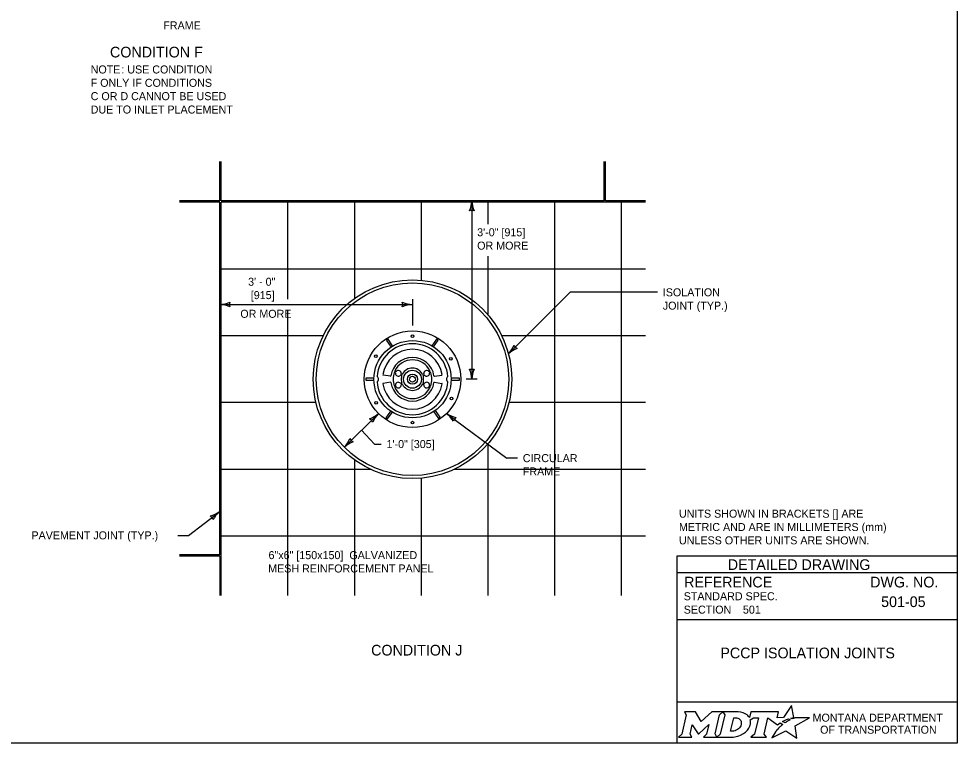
# Model space of a CAD drawing. Extents: x 49991.4 to 50021, y 49987.6 to 50011.4.
# Drawn here: x 50009.72 to 50016.75, y 49987.8 to 49993.22 of the extents above; entities that cross this region are included whole.
import ezdxf

# ---------------------------------------------------------------- set-up
doc = ezdxf.new("R2010")
doc.units = 0
for name, color, linetype in [('Default', 7, 'Continuous'), ('Level 1', 7, 'Continuous'), ('Level 15', 7, 'Continuous'), ('Level 2', 7, 'Continuous'), ('Level 3', 7, 'Continuous'), ('Level 4', 7, 'Continuous'), ('Level 5', 7, 'Continuous'), ('W35', 7, 'Continuous')]:
    doc.layers.add(name, color=color, linetype=linetype)

msp = doc.modelspace()

# ---------------------------------------------------------------- linework, layer by layer
at = {"layer": 'Default'}
for points in [[(50015.5126, 49987.9811), (50015.5023, 49987.9867), (50015.5139, 49987.9895), (50015.5255, 49987.9915), (50015.5081, 49988.0816), (50015.4486, 49987.9903), (50015.4013, 49987.9896), (50015.4116, 49988.0337), (50015.2024, 49988.0338), (50015.1923, 49987.9913), (50015.1865, 49987.9996)], [(50014.7056, 49988.0338), (50014.7197, 49988.0104), (50014.6862, 49987.8671), (50014.6605, 49987.8446), (50014.7621, 49987.8446), (50014.7486, 49987.8674), (50014.7648, 49987.9375), (50014.8085, 49987.8685), (50014.8138, 49987.8685), (50014.8889, 49987.938), (50014.8725, 49987.8669), (50014.8478, 49987.8449), (50014.9494, 49987.8449), (50014.9356, 49987.8682), (50014.9688, 49988.0106)], [(50014.9688, 49988.0106), (50014.9941, 49988.0338), (50014.9117, 49988.0338), (50014.8321, 49987.9608), (50014.7876, 49988.0335), (50014.7056, 49988.0338)], [(50015.1077, 49988.0338), (50014.9941, 49988.0338), (50015.0088, 49988.0109), (50014.9749, 49987.8671), (50014.9494, 49987.8449), (50015.06, 49987.8449)], [(50015.1317, 49987.9471), (50015.1305, 49987.939), (50015.1273, 49987.9297), (50015.1231, 49987.9215), (50015.1175, 49987.914), (50015.111, 49987.9071), (50015.1031, 49987.9008), (50015.0948, 49987.8961), (50015.0857, 49987.8922), (50015.0766, 49987.8899), (50015.0674, 49987.889), (50015.0515, 49987.889), (50015.0751, 49987.989), (50015.0911, 49987.989), (50015.0987, 49987.9884), (50015.1063, 49987.9865), (50015.1129, 49987.9835), (50015.119, 49987.9793), (50015.1238, 49987.9743), (50015.1275, 49987.9683), (50015.1302, 49987.9621), (50015.1318, 49987.9547), (50015.1318, 49987.9517), (50015.1317, 49987.9471)], [(50015.1991, 49987.9747), (50015.2237, 49987.9878), (50015.2606, 49987.9878), (50015.232, 49987.8673), (50015.2045, 49987.8446), (50015.3207, 49987.8446), (50015.3037, 49987.8675), (50015.3319, 49987.9877), (50015.4032, 49987.936), (50015.4243, 49987.9511), (50015.444, 49987.9402)], [(50015.3882, 49987.8843), (50015.3729, 49987.8599), (50015.3682, 49987.8524), (50015.3624, 49987.8438), (50015.3601, 49987.8395), (50015.4654, 49987.8926), (50015.5493, 49987.8375), (50015.5362, 49987.9302), (50015.6431, 49987.9886), (50015.5938, 49987.9894), (50015.5637, 49987.9898), (50015.5429, 49987.9901), (50015.5361, 49987.9886), (50015.5312, 49987.9874), (50015.5228, 49987.9851), (50015.5126, 49987.9811)], [(50015.4622, 49987.9535), (50015.4598, 49987.9518), (50015.4415, 49987.9614), (50015.4518, 49987.9671), (50015.4559, 49987.9693), (50015.4645, 49987.9733), (50015.4702, 49987.9759), (50015.4781, 49987.9789), (50015.4854, 49987.9816), (50015.4972, 49987.9742), (50015.4932, 49987.9721), (50015.4886, 49987.9696), (50015.4844, 49987.9674), (50015.4794, 49987.9645), (50015.4775, 49987.9634), (50015.4748, 49987.9618), (50015.4723, 49987.9604), (50015.47, 49987.9588), (50015.4674, 49987.957), (50015.4647, 49987.9552), (50015.4622, 49987.9535)], [(50015.1057, 49987.8522), (50015.1141, 49987.8548), (50015.1271, 49987.8602), (50015.1475, 49987.8712)], [(50015.4021, 49987.9004), (50015.4021, 49987.9004)]]:
    msp.add_lwpolyline(points, dxfattribs=at)
for centre, radius, start, end in [((50015.0868, 49987.9727), 0.1183, 300.91025, 339.13831), ((50015.1308, 49987.9554), 0.0709, 339.53292, 15.85821)]:
    msp.add_arc(centre, radius, start, end, dxfattribs=at)
for centre, major_axis, ratio, start_param, end_param in [((50015.1056, 49987.9864), (0.0834, -0.0037), 0.568097, 0.61298, 1.570796), ((50015.1612, 49987.9937), (0.0361, -0.0295), 0.469099, 1.225588, 1.570796), ((50015.4119, 49987.9106), (-0.0098, -0.0102), 0.016458, 3.141593, 6.279097), ((50015.4329, 49987.9305), (-0.0112, -0.0097), 0.021651, 3.157348, 6.283185), ((50015.0603, 49987.9932), (0, 0.1484), 0.987302, 3.139398, 3.456847), ((50015.3952, 49987.8923), (-0.00694, -0.00806), 0.008222, 0, 3.137361)]:
    msp.add_ellipse(centre, major_axis=major_axis, ratio=ratio, start_param=start_param, end_param=end_param, dxfattribs=at)
at = {"layer": 'Level 1'}
for p, q in [((50011.2232, 49991.862), (50011.2232, 49992.1547)), ((50011.2352, 49991.862), (50011.2352, 49992.1547)), ((50014.1032, 49991.862), (50014.1032, 49992.1547)), ((50014.1152, 49991.862), (50014.1152, 49992.1547)), ((50011.2232, 49991.862), (50010.9216, 49991.862)), ((50014.1032, 49991.862), (50011.2352, 49991.862)), ((50014.4142, 49991.862), (50014.1152, 49991.862)), ((50011.2232, 49991.85), (50010.9216, 49991.85)), ((50011.2232, 49989.8793), (50011.2232, 49991.85)), ((50014.4142, 49991.85), (50011.2352, 49991.85)), ((50011.2352, 49988.9044), (50011.2352, 49991.85)), ((50012.5032, 49990.548), (50012.4486, 49990.5557)), ((50012.5388, 49990.5737), (50012.5347, 49990.5754)), ((50012.5421, 49990.5816), (50012.538, 49990.5833)), ((50012.5865, 49990.5539), (50012.5813, 49990.5561)), ((50012.5898, 49990.5619), (50012.5846, 49990.564)), ((50012.746, 49990.5619), (50012.7512, 49990.564)), ((50012.7493, 49990.5539), (50012.7544, 49990.5561)), ((50012.7937, 49990.5816), (50012.7978, 49990.5833)), ((50012.797, 49990.5737), (50012.8011, 49990.5754)), ((50012.8325, 49990.548), (50012.8871, 49990.5557)), ((50012.5032, 49990.5017), (50012.4486, 49990.494)), ((50012.5388, 49990.476), (50012.5347, 49990.4743)), ((50012.5421, 49990.4681), (50012.538, 49990.4664)), ((50012.5865, 49990.4958), (50012.5813, 49990.4937)), ((50012.5898, 49990.4879), (50012.5846, 49990.4857)), ((50012.746, 49990.4879), (50012.7512, 49990.4857)), ((50012.7493, 49990.4958), (50012.7544, 49990.4937)), ((50012.7937, 49990.4681), (50012.7978, 49990.4664)), ((50012.797, 49990.476), (50012.8011, 49990.4743)), ((50012.8325, 49990.5017), (50012.8871, 49990.494)), ((50011.2232, 49989.209), (50011.2232, 49989.8793)), ((50011.2232, 49989.209), (50010.9216, 49989.209)), ((50011.2232, 49989.1997), (50010.9216, 49989.1997)), ((50011.2232, 49989.1997), (50011.2232, 49988.9044))]:
    msp.add_line(p, q, dxfattribs=at)
msp.add_lwpolyline([(49999.3835, 49998.9992), (50016.7501, 49998.9992), (50016.7501, 49987.7988), (49999.3835, 49987.7988)], close=True, dxfattribs=at)
for points in [[(50012.5195, 49990.7743), (50012.4847, 49990.824), (50012.4723, 49990.8153), (50012.5071, 49990.7657)], [(50012.5195, 49990.7743), (50012.4847, 49990.824), (50012.4723, 49990.8153), (50012.5071, 49990.7657)], [(50012.8258, 49990.7669), (50012.8606, 49990.8165), (50012.8482, 49990.8252), (50012.8134, 49990.7755)], [(50012.8258, 49990.7669), (50012.8606, 49990.8165), (50012.8482, 49990.8252), (50012.8134, 49990.7755)], [(50012.3791, 49990.5328), (50012.3185, 49990.5328), (50012.3185, 49990.5177), (50012.3791, 49990.5177)], [(50012.9596, 49990.5169), (50013.0202, 49990.5169), (50013.0202, 49990.532), (50012.9596, 49990.532)], [(50012.5031, 49990.2855), (50012.4683, 49990.2359), (50012.4807, 49990.2272), (50012.5154, 49990.2768)], [(50012.5031, 49990.2855), (50012.4683, 49990.2359), (50012.4807, 49990.2272), (50012.5154, 49990.2768)], [(50012.8279, 49990.2809), (50012.8626, 49990.2312), (50012.875, 49990.2399), (50012.8403, 49990.2896)], [(50012.8279, 49990.2809), (50012.8626, 49990.2312), (50012.875, 49990.2399), (50012.8403, 49990.2896)]]:
    msp.add_lwpolyline(points, dxfattribs=at)
for centre, radius in [((50012.6679, 49990.5249), 0.7438), ((50012.6679, 49990.5249), 0.7213), ((50012.6685, 49990.525), 0.3619), ((50012.6685, 49990.525), 0.3619), ((50012.6685, 49990.525), 0.2895), ((50012.6685, 49990.525), 0.2895), ((50012.6685, 49990.8471), 0.00988), ((50012.3927, 49990.6974), 0.00988), ((50012.9559, 49990.6774), 0.00988), ((50012.6679, 49990.5249), 0.0672), ((50012.6679, 49990.5249), 0.0381), ((50012.6679, 49990.5249), 0.0221), ((50012.9599, 49990.3806), 0.00988), ((50012.3957, 49990.3479), 0.00988), ((50012.6685, 49990.1998), 0.00988)]:
    msp.add_circle(centre, radius, dxfattribs=at)
for centre, radius, start, end in [((50012.6679, 49990.5249), 0.2656, 4.13676, 175.86322), ((50012.6679, 49990.5249), 0.2243, 8.74918, 171.25082), ((50012.6679, 49990.5249), 0.1634, 8.99765, 171.00235), ((50012.6679, 49990.5249), 0.1454, 90, 154.63538), ((50012.6679, 49990.5249), 0.1454, 25.36457, 90), ((50012.5617, 49990.5688), 0.0213, 354.70438, 140.29581), ((50012.6679, 49990.5249), 0.0838, 90, 152.78109), ((50012.6679, 49990.5249), 0.0838, 27.21891, 90), ((50012.7741, 49990.5688), 0.0213, 39.70419, 185.29564), ((50012.3909, 49990.5249), 0.0226, 302.04668, 57.95332), ((50012.449, 49990.5585), 0.0029, 171.25152, 262.00056), ((50012.5036, 49990.5509), 0.0029, 262.00056, 351.00138), ((50012.6679, 49990.5249), 0.1454, 160.36454, 179.99994), ((50012.6679, 49990.5249), 0.1454, 179.99994, 199.63538), ((50012.5336, 49990.5728), 0.00283, 67.50047, 160.36529), ((50012.5391, 49990.5859), 0.00283, 154.63452, 247.50047), ((50012.5377, 49990.5711), 0.00283, 354.70324, 67.50047), ((50012.5617, 49990.5688), 0.0213, 174.70396, 320.29581), ((50012.5432, 49990.5842), 0.00283, 247.50047, 320.29757), ((50012.5802, 49990.5534), 0.00283, 67.50047, 140.29757), ((50012.5857, 49990.5666), 0.00283, 174.70324, 247.50047), ((50012.6679, 49990.5249), 0.0838, 162.2189, 180), ((50012.6679, 49990.5249), 0.0838, 180, 197.781), ((50012.5854, 49990.5513), 0.00283, 342.21869, 67.50047), ((50012.5909, 49990.5645), 0.00283, 247.50047, 332.78143), ((50012.7449, 49990.5645), 0.00283, 207.21857, 292.49953), ((50012.7503, 49990.5513), 0.00283, 112.49953, 197.78178), ((50012.6679, 49990.5249), 0.0838, 0, 17.7811), ((50012.6679, 49990.5249), 0.0838, 342.2189, 0), ((50012.7501, 49990.5666), 0.00283, 292.50097, 5.2969), ((50012.7555, 49990.5534), 0.00283, 39.70343, 112.50097), ((50012.7741, 49990.5688), 0.0213, 219.70419, 5.29606), ((50012.7926, 49990.5842), 0.00283, 219.70343, 292.50097), ((50012.798, 49990.5711), 0.00283, 112.50097, 185.2969), ((50012.7967, 49990.5859), 0.00283, 292.50097, 25.36548), ((50012.8022, 49990.5728), 0.00283, 19.63471, 112.50097), ((50012.6679, 49990.5249), 0.1454, 0, 19.63545), ((50012.6679, 49990.5249), 0.1454, 340.36455, 0), ((50012.8321, 49990.5509), 0.0029, 188.99862, 277.99944), ((50012.8867, 49990.5585), 0.0029, 277.99944, 8.74848), ((50012.9448, 49990.5249), 0.0226, 122.04687, 237.95313), ((50012.6679, 49990.5249), 0.2656, 184.13678, 355.86324), ((50012.449, 49990.4912), 0.0029, 97.99944, 188.74848), ((50012.6679, 49990.5249), 0.2243, 188.74918, 351.25086), ((50012.5036, 49990.4989), 0.0029, 8.99862, 97.99944), ((50012.6679, 49990.5249), 0.1634, 188.99765, 351.0024), ((50012.5336, 49990.477), 0.00283, 199.63471, 292.49953), ((50012.5391, 49990.4638), 0.00283, 112.49953, 205.36548), ((50012.6679, 49990.5249), 0.1454, 205.36462, 270), ((50012.5377, 49990.4787), 0.00283, 292.49953, 5.29676), ((50012.5617, 49990.4809), 0.0213, 39.70419, 185.29604), ((50012.5432, 49990.4655), 0.00283, 39.70243, 112.49953), ((50012.5617, 49990.4809), 0.0213, 219.70419, 5.29562), ((50012.5802, 49990.4963), 0.00283, 219.70243, 292.49953), ((50012.5857, 49990.4831), 0.00283, 112.49953, 185.29676), ((50012.5854, 49990.4984), 0.00283, 292.49953, 17.78131), ((50012.5909, 49990.4852), 0.00283, 27.21857, 112.49953), ((50012.6679, 49990.5249), 0.0838, 207.21891, 270), ((50012.6679, 49990.5249), 0.0838, 270, 332.78109), ((50012.6679, 49990.5249), 0.1454, 270, 334.63543), ((50012.7449, 49990.4852), 0.00283, 67.50047, 152.78143), ((50012.7503, 49990.4984), 0.00283, 162.21822, 247.50047), ((50012.7501, 49990.4831), 0.00283, 354.7031, 67.49903), ((50012.7741, 49990.4809), 0.0213, 174.70436, 320.29581), ((50012.7555, 49990.4963), 0.00283, 247.49903, 320.29657), ((50012.7741, 49990.4809), 0.0213, 354.70394, 140.29581), ((50012.7926, 49990.4655), 0.00283, 67.49903, 140.29657), ((50012.798, 49990.4787), 0.00283, 174.7031, 247.49903), ((50012.7967, 49990.4638), 0.00283, 334.63452, 67.49903), ((50012.8022, 49990.477), 0.00283, 247.49903, 340.36529), ((50012.8321, 49990.4989), 0.0029, 82.00056, 171.00138), ((50012.8867, 49990.4912), 0.0029, 351.25152, 82.00056)]:
    msp.add_arc(centre, radius, start, end, dxfattribs=at)
at = {"layer": 'Level 15'}
msp.add_line((50010.9891, 49989.3556), (50011.2232, 49989.5335), dxfattribs=at)
at = {"layer": 'Level 2'}
for p in [(50013.3873, 49990.714), (50014.5039, 49991.1757)]:
    msp.add_line(p, (50013.8495, 49991.1757), dxfattribs=at)
at = {"layer": 'Level 3'}
for p, q in [((50013.1128, 49991.862), (50013.1128, 49990.5249)), ((50011.2232, 49991.0849), (50012.6679, 49991.0849)), ((50012.6679, 49991.1249), (50012.6679, 49990.9262)), ((50013.1528, 49990.5249), (50013.0692, 49990.5249)), ((50012.4124, 49990.2694), (50012.1578, 49990.0148)), ((50012.9234, 49990.2694), (50013.3748, 49989.9339)), ((50012.2851, 49990.1421), (50012.3833, 49990.0392)), ((50012.3833, 49990.0392), (50012.4335, 49990.0392)), ((50013.4548, 49989.9339), (50013.3748, 49989.9339)), ((50010.9091, 49989.3556), (50010.9891, 49989.3556))]:
    msp.add_line(p, q, dxfattribs=at)
for centre, radius, start, end in [((50012.8906, 49991.8712), 0.2223, 337.45601, 357.63952), ((50013.3455, 49991.8735), 0.233, 182.82731, 202.07716), ((50013.1128, 49991.7338), 0.0548, 72.13882, 107.86118), ((50011.2117, 49991.3176), 0.233, 272.82731, 292.07716), ((50011.214, 49990.8627), 0.2223, 67.45601, 87.63952), ((50011.3514, 49991.0849), 0.0548, 162.13882, 197.86118), ((50012.677, 49991.307), 0.2223, 247.45601, 267.63952), ((50012.5397, 49991.0849), 0.0548, 342.13882, 17.86118), ((50012.6794, 49990.8521), 0.233, 92.82731, 112.07716), ((50013.2147, 49990.8706), 0.233, 317.79151, 337.04136), ((50013.5377, 49990.5504), 0.2223, 112.42021, 132.60372), ((50013.478, 49990.8046), 0.0548, 207.10302, 242.82538), ((50013.1128, 49990.6531), 0.0548, 252.13882, 287.86118), ((50012.8801, 49990.5134), 0.233, 2.82731, 22.07716), ((50013.3349, 49990.5157), 0.2223, 157.45601, 177.63952), ((50012.2618, 49990.4329), 0.2223, 292.45601, 312.63952), ((50012.5851, 49990.1129), 0.233, 137.82731, 157.07716), ((50012.7835, 49990.0965), 0.2223, 30.83963, 51.02314), ((50013.053, 49990.463), 0.233, 236.21093, 255.46078), ((50013.0263, 49990.1929), 0.0548, 125.52244, 161.2448), ((50012.3217, 49990.1787), 0.0548, 27.13882, 62.86118), ((50011.9851, 49990.1712), 0.233, 317.82731, 337.07716), ((50012.3084, 49989.8513), 0.2223, 112.45601, 132.63952), ((50012.2485, 49990.1055), 0.0548, 207.13882, 242.86118), ((50011.096, 49989.7159), 0.2223, 284.69956, 304.88307), ((50011.3732, 49989.3552), 0.233, 130.07086, 149.32071), ((50011.1211, 49989.4559), 0.0548, 19.38237, 55.10473)]:
    msp.add_arc(centre, radius, start, end, dxfattribs=at)
at = {"layer": 'Level 4'}
for p, q in [((50011.7352, 49991.1249), (50011.7352, 49991.85)), ((50012.2352, 49991.1299), (50012.2352, 49991.85)), ((50012.7352, 49991.2656), (50012.7352, 49991.85)), ((50013.2352, 49991.6854), (50013.2352, 49991.85)), ((50013.7352, 49988.9044), (50013.7352, 49991.85)), ((50014.2352, 49988.9044), (50014.2352, 49991.85)), ((50013.2352, 49991.0059), (50013.2352, 49991.4454)), ((50014.4142, 49991.35), (50011.2352, 49991.35)), ((50011.7352, 49988.9044), (50011.7352, 49991.0449)), ((50011.9989, 49990.85), (50011.2352, 49990.85)), ((50014.4142, 49990.85), (50013.3369, 49990.85)), ((50011.9449, 49990.35), (50011.2352, 49990.35)), ((50014.4142, 49990.35), (50013.3909, 49990.35)), ((50013.2352, 49988.9044), (50013.2352, 49990.0438)), ((50012.2352, 49988.9044), (50012.2352, 49989.9198)), ((50012.355, 49989.85), (50011.2352, 49989.85)), ((50014.4142, 49989.85), (50012.9808, 49989.85)), ((50012.7352, 49988.9044), (50012.7352, 49989.7841)), ((50014.4142, 49989.35), (50011.2352, 49989.35))]:
    msp.add_line(p, q, dxfattribs=at)
at = {"layer": 'Level 5'}
for p, q in [((50016.7501, 49989.1988), (50014.6501, 49989.1988)), ((50014.6501, 49989.1988), (50014.6501, 49987.7988)), ((50016.7501, 49989.0738), (50014.6501, 49989.0738)), ((50016.3862, 49988.8587), (50016.3862, 49988.8587)), ((50015.1444, 49988.7993), (50015.1444, 49988.7993)), ((50016.7501, 49988.7238), (50014.6501, 49988.7238)), ((50015.7001, 49988.4747), (50015.7001, 49988.4747)), ((50016.7501, 49988.1057), (50014.6501, 49988.1057))]:
    msp.add_line(p, q, dxfattribs=at)
at = {"layer": 'W35'}
for points in [[(50012.3791, 49990.5328), (50012.3185, 49990.5328), (50012.3185, 49990.5177), (50012.3791, 49990.5177)], [(50012.9596, 49990.5169), (50013.0202, 49990.5169), (50013.0202, 49990.532), (50012.9596, 49990.532)]]:
    msp.add_lwpolyline(points, dxfattribs=at)

# ---------------------------------------------------------------- texts
at = {"layer": 'Default'}
for s, p in [('MONTANA DEPARTMENT', (50015.6663, 49987.96)), ('OF TRANSPORTATION', (50015.7225, 49987.87))]:
    msp.add_text(s, height=0.06, dxfattribs=at).set_placement(p)
at = {"layer": 'Level 2'}
for s, height, p in [('FRAME', 0.06, (50010.8008, 49993.1448)), ('CONDITION F', 0.08, (50010.4014, 49992.9348)), ('NOTE', 0.06, (50010.2566, 49992.8148)), (': USE CONDITION', 0.06, (50010.4865, 49992.8148)), ('F ONLY IF CONDITIONS', 0.06, (50010.2566, 49992.7148)), ('C OR D CANNOT BE USED', 0.06, (50010.2566, 49992.6148)), ('DUE TO INLET PLACEMENT', 0.06, (50010.2566, 49992.5148)), ('3\'-0" [915]', 0.06, (50013.1528, 49991.5954)), ('OR MORE', 0.06, (50013.1528, 49991.4954)), ('3\' - 0"', 0.06, (50011.4362, 49991.2249)), ('[915]', 0.06, (50011.4565, 49991.1249)), ('ISOLATION ', 0.06, (50014.5439, 49991.1457)), ('JOINT (TYP.)', 0.06, (50014.5439, 49991.0457)), ('OR MORE', 0.06, (50011.378, 49990.9849)), ('1\'-0" [305]', 0.06, (50012.4735, 49990.0092)), ('CIRCULAR', 0.06, (50013.4948, 49989.9039)), ('FRAME', 0.06, (50013.4948, 49989.8039)), ('UNITS SHOWN IN BRACKETS [] ARE ', 0.06, (50014.6651, 49989.488)), ('METRIC AND ARE IN MILLIMETERS (mm) ', 0.06, (50014.6651, 49989.388)), ('PAVEMENT JOINT (TYP.)', 0.06, (50009.8128, 49989.3256)), ('UNLESS OTHER UNITS ARE SHOWN.', 0.06, (50014.6651, 49989.288)), ('6"x6" [150x150]  GALVANIZED', 0.06, (50011.5892, 49989.1774)), ('MESH REINFORCEMENT PANEL', 0.06, (50011.5866, 49989.0774)), ('501', 0.06, (50015.1444, 49988.7693)), ('501-05', 0.08, (50016.1798, 49988.8187)), ('CONDITION J', 0.08, (50012.3583, 49988.4555)), ('PCCP ISOLATION JOINTS', 0.08, (50014.9752, 49988.4347))]:
    msp.add_text(s, height=height, dxfattribs=at).set_placement(p)
at = {"layer": 'Level 5'}
for s, height, p in [('DETAILED DRAWING', 0.0799, (50015.0311, 49989.0963)), ('REFERENCE', 0.08, (50014.7037, 49988.9654)), ('DWG. NO.', 0.08, (50016.0979, 49988.9654)), ('STANDARD SPEC.', 0.06, (50014.7004, 49988.8694)), ('SECTION', 0.06, (50014.7004, 49988.7694))]:
    msp.add_text(s, height=height, dxfattribs=at).set_placement(p)

doc.saveas('drawing.dxf')
